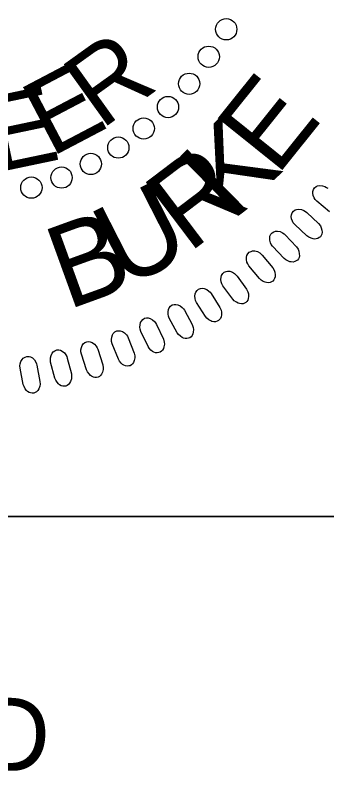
# Model space of a CAD drawing. Extents: x 505602 to 507705, y 483109 to 484209.
# Drawn here: x 507224.6 to 507248.1, y 484026.9 to 484083.9 of the extents above; entities that cross this region are included whole.
import ezdxf

# ---------------------------------------------------------------- set-up
doc = ezdxf.new("R2010")
doc.units = 0
for name, color, linetype in [('Sheet PE Seal Cell', 7, 'Continuous'), ('Sheet Profile CELL', 7, 'Continuous'), ('Sheet Sticker Exception Certification CELL', 7, 'Continuous')]:
    doc.layers.add(name, color=color, linetype=linetype)

msp = doc.modelspace()

# ---------------------------------------------------------------- linework, layer by layer
at = {"layer": 'Sheet PE Seal Cell'}
msp.add_lwpolyline([(507248.314, 484069.095), (507247.341, 484069.891), (507247.225, 484070.016), (507247.146, 484070.14), (507247.08, 484070.31), (507247.044, 484070.486), (507247.045, 484070.612), (507247.098, 484070.771), (507247.179, 484070.899), (507247.305, 484070.988), (507247.41, 484071.037), (507247.567, 484071.072), (507247.774, 484071.056), (507247.956, 484070.993), (507248.074, 484070.933), (507248.184, 484070.862)], dxfattribs=at)
for points in [[(507246.59, 484069.051), (507247.483, 484068.211), (507247.618, 484068.034), (507247.684, 484067.9), (507247.731, 484067.702), (507247.744, 484067.556), (507247.725, 484067.419), (507247.683, 484067.316), (507247.62, 484067.221), (507247.529, 484067.153), (507247.425, 484067.086), (507247.311, 484067.05), (507247.166, 484067.043), (507247.067, 484067.054), (507246.911, 484067.107), (507246.74, 484067.186), (507246.608, 484067.279), (507245.687, 484068.134), (507245.579, 484068.267), (507245.508, 484068.396), (507245.453, 484068.57), (507245.428, 484068.747), (507245.437, 484068.873), (507245.5, 484069.028), (507245.589, 484069.151), (507245.72, 484069.232), (507245.828, 484069.274), (507245.988, 484069.299), (507246.193, 484069.269), (507246.37, 484069.196), (507246.485, 484069.129)], [(507244.977, 484067.357), (507245.817, 484066.463), (507245.94, 484066.277), (507245.998, 484066.139), (507246.032, 484065.939), (507246.036, 484065.792), (507246.008, 484065.657), (507245.96, 484065.557), (507245.891, 484065.465), (507245.796, 484065.404), (507245.688, 484065.344), (507245.572, 484065.315), (507245.426, 484065.317), (507245.328, 484065.334), (507245.177, 484065.397), (507245.01, 484065.487), (507244.885, 484065.588), (507244.019, 484066.499), (507243.92, 484066.638), (507243.857, 484066.771), (507243.813, 484066.948), (507243.799, 484067.126), (507243.816, 484067.251), (507243.889, 484067.403), (507243.985, 484067.519), (507244.121, 484067.592), (507244.231, 484067.627), (507244.392, 484067.642), (507244.595, 484067.601), (507244.768, 484067.515), (507244.878, 484067.442)], [(507243.245, 484065.828), (507244.027, 484064.882), (507244.138, 484064.689), (507244.186, 484064.549), (507244.208, 484064.346), (507244.203, 484064.2), (507244.167, 484064.067), (507244.112, 484063.97), (507244.039, 484063.883), (507243.94, 484063.827), (507243.828, 484063.774), (507243.71, 484063.753), (507243.565, 484063.763), (507243.468, 484063.786), (507243.321, 484063.859), (507243.16, 484063.96), (507243.042, 484064.068), (507242.235, 484065.031), (507242.145, 484065.177), (507242.09, 484065.313), (507242.058, 484065.493), (507242.055, 484065.672), (507242.079, 484065.795), (507242.162, 484065.941), (507242.264, 484066.052), (507242.405, 484066.116), (507242.518, 484066.145), (507242.679, 484066.149), (507242.879, 484066.095), (507243.046, 484065.999), (507243.151, 484065.918)], [(507241.339, 484064.262), (507242.059, 484063.269), (507242.158, 484063.07), (507242.198, 484062.927), (507242.207, 484062.724), (507242.192, 484062.577), (507242.149, 484062.446), (507242.087, 484062.353), (507242.008, 484062.271), (507241.906, 484062.222), (507241.792, 484062.176), (507241.672, 484062.162), (507241.528, 484062.182), (507241.433, 484062.211), (507241.29, 484062.293), (507241.137, 484062.403), (507241.025, 484062.518), (507240.28, 484063.531), (507240.199, 484063.681), (507240.154, 484063.821), (507240.132, 484064.002), (507240.141, 484064.181), (507240.173, 484064.303), (507240.264, 484064.444), (507240.374, 484064.548), (507240.519, 484064.603), (507240.632, 484064.624), (507240.794, 484064.619), (507240.99, 484064.552), (507241.151, 484064.446), (507241.25, 484064.358)], [(507239.395, 484062.934), (507240.052, 484061.898), (507240.138, 484061.693), (507240.168, 484061.547), (507240.164, 484061.343), (507240.141, 484061.198), (507240.089, 484061.071), (507240.023, 484060.981), (507239.938, 484060.904), (507239.833, 484060.862), (507239.716, 484060.822), (507239.595, 484060.817), (507239.454, 484060.845), (507239.36, 484060.88), (507239.223, 484060.971), (507239.076, 484061.09), (507238.972, 484061.213), (507238.293, 484062.27), (507238.221, 484062.425), (507238.185, 484062.567), (507238.175, 484062.75), (507238.194, 484062.928), (507238.234, 484063.047), (507238.334, 484063.182), (507238.45, 484063.279), (507238.598, 484063.326), (507238.713, 484063.339), (507238.873, 484063.324), (507239.065, 484063.244), (507239.219, 484063.128), (507239.313, 484063.035)], [(507237.376, 484061.678), (507237.966, 484060.602), (507238.039, 484060.392), (507238.061, 484060.245), (507238.044, 484060.042), (507238.012, 484059.899), (507237.952, 484059.775), (507237.879, 484059.69), (507237.79, 484059.618), (507237.683, 484059.582), (507237.564, 484059.551), (507237.443, 484059.552), (507237.304, 484059.59), (507237.213, 484059.631), (507237.081, 484059.73), (507236.943, 484059.858), (507236.846, 484059.987), (507236.235, 484061.085), (507236.173, 484061.244), (507236.145, 484061.389), (507236.147, 484061.571), (507236.177, 484061.748), (507236.224, 484061.865), (507236.333, 484061.993), (507236.455, 484062.082), (507236.605, 484062.119), (507236.721, 484062.126), (507236.88, 484062.1), (507237.066, 484062.008), (507237.212, 484061.883), (507237.3, 484061.784)], [(507235.274, 484060.614), (507235.796, 484059.504), (507235.855, 484059.29), (507235.868, 484059.141), (507235.839, 484058.94), (507235.797, 484058.799), (507235.729, 484058.679), (507235.652, 484058.599), (507235.558, 484058.533), (507235.449, 484058.504), (507235.328, 484058.48), (507235.208, 484058.489), (507235.071, 484058.535), (507234.982, 484058.581), (507234.858, 484058.688), (507234.728, 484058.825), (507234.639, 484058.96), (507234.098, 484060.094), (507234.046, 484060.257), (507234.027, 484060.403), (507234.041, 484060.585), (507234.083, 484060.759), (507234.137, 484060.873), (507234.253, 484060.994), (507234.38, 484061.076), (507234.532, 484061.103), (507234.648, 484061.102), (507234.805, 484061.067), (507234.986, 484060.964), (507235.124, 484060.829), (507235.205, 484060.725)], [(507233.146, 484059.607), (507233.597, 484058.466), (507233.643, 484058.249), (507233.646, 484058.1), (507233.604, 484057.9), (507233.554, 484057.763), (507233.479, 484057.648), (507233.397, 484057.572), (507233.299, 484057.512), (507233.188, 484057.49), (507233.066, 484057.473), (507232.946, 484057.49), (507232.813, 484057.545), (507232.727, 484057.597), (507232.61, 484057.711), (507232.489, 484057.856), (507232.409, 484057.996), (507231.94, 484059.162), (507231.898, 484059.328), (507231.889, 484059.474), (507231.913, 484059.656), (507231.966, 484059.826), (507232.027, 484059.937), (507232.15, 484060.05), (507232.283, 484060.124), (507232.436, 484060.142), (507232.553, 484060.133), (507232.707, 484060.088), (507232.88, 484059.974), (507233.01, 484059.832), (507233.084, 484059.722)], [(507230.854, 484058.748), (507231.232, 484057.581), (507231.265, 484057.362), (507231.258, 484057.213), (507231.204, 484057.016), (507231.145, 484056.882), (507231.063, 484056.771), (507230.976, 484056.701), (507230.875, 484056.648), (507230.763, 484056.632), (507230.64, 484056.624), (507230.522, 484056.648), (507230.392, 484056.711), (507230.31, 484056.768), (507230.2, 484056.89), (507230.087, 484057.042), (507230.017, 484057.187), (507229.622, 484058.38), (507229.591, 484058.548), (507229.591, 484058.695), (507229.626, 484058.874), (507229.69, 484059.041), (507229.758, 484059.147), (507229.889, 484059.253), (507230.025, 484059.318), (507230.179, 484059.326), (507230.294, 484059.31), (507230.446, 484059.256), (507230.611, 484059.131), (507230.731, 484058.981), (507230.8, 484058.867)], [(507228.562, 484058.077), (507228.867, 484056.888), (507228.885, 484056.667), (507228.869, 484056.518), (507228.803, 484056.326), (507228.736, 484056.196), (507228.647, 484056.091), (507228.556, 484056.026), (507228.451, 484055.979), (507228.339, 484055.971), (507228.215, 484055.97), (507228.099, 484056.001), (507227.972, 484056.072), (507227.895, 484056.135), (507227.792, 484056.263), (507227.69, 484056.422), (507227.629, 484056.571), (507227.309, 484057.786), (507227.289, 484057.956), (507227.298, 484058.102), (507227.345, 484058.28), (507227.419, 484058.442), (507227.493, 484058.544), (507227.63, 484058.641), (507227.771, 484058.697), (507227.925, 484058.695), (507228.039, 484058.673), (507228.187, 484058.609), (507228.344, 484058.474), (507228.455, 484058.317), (507228.516, 484058.199)], [(507226.276, 484057.539), (507226.505, 484056.333), (507226.51, 484056.111), (507226.485, 484055.964), (507226.407, 484055.777), (507226.331, 484055.651), (507226.236, 484055.551), (507226.141, 484055.492), (507226.034, 484055.452), (507225.921, 484055.451), (507225.798, 484055.458), (507225.683, 484055.497), (507225.562, 484055.576), (507225.488, 484055.642), (507225.394, 484055.777), (507225.302, 484055.942), (507225.25, 484056.095), (507225.008, 484057.328), (507224.998, 484057.498), (507225.016, 484057.644), (507225.074, 484057.817), (507225.158, 484057.975), (507225.239, 484058.072), (507225.381, 484058.16), (507225.525, 484058.208), (507225.679, 484058.196), (507225.791, 484058.167), (507225.935, 484058.093), (507226.084, 484057.949), (507226.184, 484057.784), (507226.237, 484057.663)]]:
    msp.add_lwpolyline(points, close=True, dxfattribs=at)
for centre in [(507240.526, 484082.835), (507239.212, 484080.763), (507237.738, 484078.732), (507236.145, 484076.98), (507234.316, 484075.364), (507232.404, 484073.93), (507230.334, 484072.696), (507228.127, 484071.674), (507225.857, 484070.917)]:
    msp.add_circle(centre, 0.801, dxfattribs=at)
at = {"layer": 'Sheet Profile CELL'}
msp.add_lwpolyline([(507169.08, 484158.662), (507269.08, 484158.662), (507269.08, 484046.162), (507169.08, 484046.162)], close=True, dxfattribs=at)
at = {"layer": 'Sheet Sticker Exception Certification CELL'}
msp.add_line((507069.03, 484046.162), (507269.067, 484046.162), dxfattribs=at)
msp.add_line((507069.03, 484046.162), (507269.067, 484046.162), dxfattribs=at)

# ---------------------------------------------------------------- texts
at = {"layer": 'Sheet PE Seal Cell'}
for s, height, rotation, p in [('R', 5.669, 35.6636, (507231.094, 484075.227)), ('E', 5.669, 27.7238, (507227.313, 484073.165)), ('E', 6.236, 51.2683, (507244.323, 484071.701)), ('E', 5.669, 11.8442, (507223.243, 484072.042)), ('K', 6.236, 44.4226, (507240.918, 484068.327)), ('R', 6.236, 37.1476, (507237.687, 484065.935)), ('U', 6.236, 27.0477, (507232.783, 484063.267)), ('B', 6.236, 19.9309, (507228.563, 484061.686))]:
    msp.add_text(s, height=height, rotation=rotation, dxfattribs=at).set_placement(p)
at = {"layer": 'Sheet Sticker Exception Certification CELL'}
msp.add_text('UNLESS ALL SIGNATURES COMPLETED', height=5.5, dxfattribs=at).set_placement((507085.03, 484027.016))
msp.add_text('UNLESS ALL SIGNATURES COMPLETED', height=5.5, dxfattribs=at).set_placement((507085.03, 484027.016))

doc.saveas('drawing.dxf')
